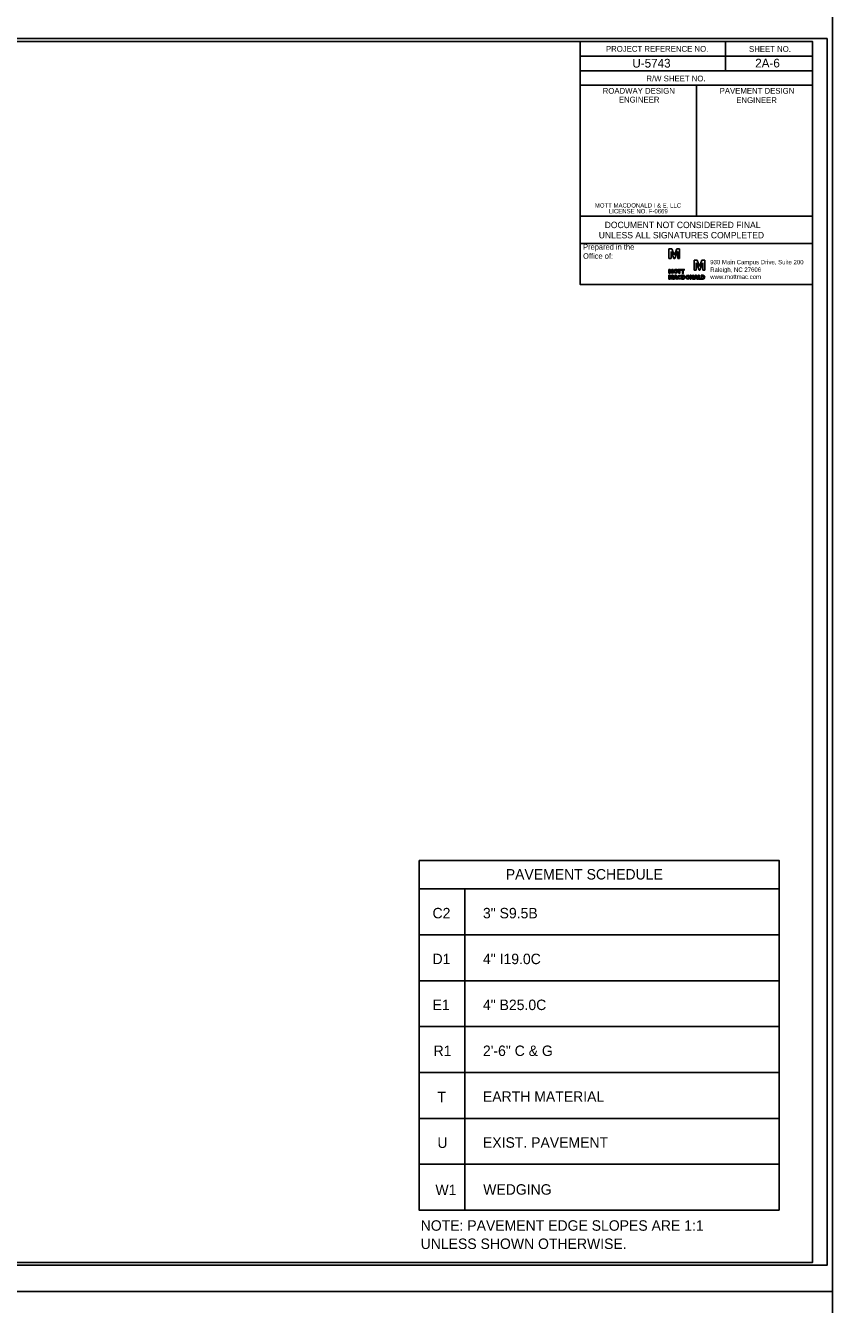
# Model space of a CAD drawing. Extents: x 1901670 to 1902225, y 193498 to 194278.
# Drawn here: x 1902064.8 to 1902134.2, y 193606.9 to 193716.9 of the extents above; entities that cross this region are included whole.
import ezdxf

# ---------------------------------------------------------------- set-up
doc = ezdxf.new("R2010")
doc.units = 0
for name, color, linetype in [('Old_Level_2', 7, 'Continuous'), ('Old_Level_42', 7, 'Continuous'), ('Old_Level_45', 7, 'Continuous'), ('Prop Dimension Text', 7, 'Continuous'), ('Prop Pavement Schedule Description CELL', 7, 'Continuous'), ('Sheet Border Standard 30in CELL', 7, 'Continuous'), ('Sheet Cutting Line CELL', 7, 'Continuous'), ('Sheet Data Field CELL', 7, 'Continuous'), ('Sheet Plot Border Inside CELL', 7, 'Continuous'), ('Sheet Plot Border Outside CELL', 7, 'Continuous'), ('Sheet Sticker Exception Certification CELL', 7, 'Continuous')]:
    doc.layers.add(name, color=color, linetype=linetype)

msp = doc.modelspace()

# ---------------------------------------------------------------- linework, layer by layer
at = {"layer": 'Old_Level_2'}
for p, q in [((1902120.44, 193697.7), (1902120.18, 193697.7)), ((1902120.18, 193697.7), (1902120.18, 193696.85)), ((1902120.18, 193696.85), (1902120.36, 193696.85)), ((1902120.36, 193696.85), (1902120.36, 193697.46)), ((1902120.36, 193697.46), (1902120.37, 193697.46)), ((1902120.37, 193697.46), (1902120.61, 193696.85)), ((1902120.64, 193697.17), (1902120.44, 193697.7)), ((1902120.61, 193696.85), (1902120.68, 193696.85)), ((1902120.65, 193697.17), (1902120.64, 193697.17)), ((1902120.64, 193697.17), (1902120.64, 193697.17)), ((1902120.85, 193697.7), (1902120.65, 193697.17)), ((1902120.65, 193697.17), (1902120.65, 193697.17)), ((1902120.68, 193696.85), (1902120.92, 193697.46)), ((1902121.1, 193697.7), (1902120.85, 193697.7)), ((1902120.92, 193697.46), (1902120.93, 193697.46)), ((1902120.93, 193697.46), (1902120.93, 193696.85)), ((1902120.93, 193696.85), (1902121.1, 193696.85)), ((1902121.1, 193696.85), (1902121.1, 193697.7)), ((1902120.28, 193695.92), (1902120.18, 193695.92)), ((1902120.18, 193695.92), (1902120.18, 193695.59)), ((1902120.25, 193695.59), (1902120.25, 193695.83)), ((1902120.25, 193695.83), (1902120.25, 193695.83)), ((1902120.25, 193695.83), (1902120.35, 193695.59)), ((1902120.25, 193695.83), (1902120.25, 193695.83)), ((1902120.36, 193695.72), (1902120.28, 193695.92)), ((1902120.44, 193695.92), (1902120.36, 193695.72)), ((1902120.38, 193695.59), (1902120.47, 193695.83)), ((1902120.54, 193695.92), (1902120.44, 193695.92)), ((1902120.47, 193695.83), (1902120.47, 193695.83)), ((1902120.47, 193695.83), (1902120.47, 193695.59)), ((1902120.47, 193695.83), (1902120.47, 193695.83)), ((1902120.47, 193695.83), (1902120.47, 193695.83)), ((1902120.54, 193695.59), (1902120.54, 193695.92)), ((1902120.54, 193695.59), (1902120.54, 193695.92)), ((1902122.6, 193696.71), (1902122.35, 193696.71)), ((1902122.35, 193696.71), (1902122.35, 193695.86)), ((1902122.35, 193695.86), (1902122.53, 193695.86)), ((1902122.53, 193695.86), (1902122.53, 193696.47)), ((1902122.53, 193696.47), (1902122.53, 193696.47)), ((1902122.53, 193696.47), (1902122.77, 193695.86)), ((1902122.8, 193696.18), (1902122.6, 193696.71)), ((1902122.77, 193695.86), (1902122.85, 193695.86)), ((1902122.81, 193696.18), (1902122.8, 193696.18)), ((1902122.8, 193696.18), (1902122.8, 193696.18)), ((1902123.01, 193696.71), (1902122.81, 193696.18)), ((1902122.81, 193696.18), (1902122.81, 193696.18)), ((1902122.85, 193695.86), (1902123.08, 193696.47)), ((1902123.27, 193696.71), (1902123.01, 193696.71)), ((1902123.08, 193696.47), (1902123.09, 193696.47)), ((1902123.09, 193696.47), (1902123.09, 193695.86)), ((1902123.09, 193695.86), (1902123.27, 193695.86)), ((1902123.27, 193695.86), (1902123.27, 193696.71)), ((1902120.18, 193695.59), (1902120.25, 193695.59)), ((1902120.28, 193695.41), (1902120.18, 193695.41)), ((1902120.18, 193695.41), (1902120.18, 193695.09)), ((1902120.18, 193695.09), (1902120.25, 193695.09)), ((1902120.25, 193695.09), (1902120.25, 193695.32)), ((1902120.25, 193695.32), (1902120.25, 193695.32)), ((1902120.25, 193695.32), (1902120.35, 193695.09)), ((1902120.36, 193695.21), (1902120.28, 193695.41)), ((1902120.35, 193695.59), (1902120.38, 193695.59)), ((1902120.35, 193695.09), (1902120.38, 193695.09)), ((1902120.44, 193695.41), (1902120.36, 193695.21)), ((1902120.38, 193695.09), (1902120.47, 193695.32)), ((1902120.54, 193695.41), (1902120.44, 193695.41)), ((1902120.47, 193695.59), (1902120.54, 193695.59)), ((1902120.47, 193695.32), (1902120.47, 193695.32)), ((1902120.47, 193695.32), (1902120.47, 193695.09)), ((1902120.47, 193695.09), (1902120.54, 193695.09)), ((1902120.54, 193695.09), (1902120.54, 193695.41)), ((1902121.22, 193695.16), (1902121.16, 193695.18)), ((1902121.22, 193695.16), (1902121.16, 193695.18)), ((1902121.17, 193695.31), (1902121.23, 193695.33)), ((1902121.17, 193695.31), (1902121.23, 193695.33)), ((1902121.42, 193695.41), (1902121.27, 193695.41)), ((1902121.27, 193695.41), (1902121.27, 193695.25)), ((1902121.27, 193695.25), (1902121.27, 193695.09)), ((1902121.27, 193695.09), (1902121.42, 193695.09)), ((1902121.34, 193695.15), (1902121.34, 193695.35)), ((1902121.34, 193695.35), (1902121.42, 193695.35)), ((1902121.42, 193695.15), (1902121.34, 193695.15)), ((1902122.96, 193695.41), (1902122.96, 193695.41)), ((1902123.1, 193695.41), (1902122.96, 193695.41)), ((1902122.96, 193695.41), (1902122.96, 193695.25)), ((1902122.96, 193695.25), (1902122.96, 193695.09)), ((1902122.96, 193695.09), (1902123.1, 193695.09)), ((1902123.02, 193695.15), (1902123.02, 193695.35)), ((1902123.02, 193695.35), (1902123.1, 193695.35)), ((1902123.1, 193695.15), (1902123.02, 193695.15)), ((1902123.1, 193695.35), (1902123.1, 193695.35))]:
    msp.add_line(p, q, dxfattribs=at)
for points in [[(1902120.95, 193695.86), (1902121.04, 193695.86), (1902121.04, 193695.59), (1902121.11, 193695.59), (1902121.11, 193695.86), (1902121.2, 193695.86), (1902121.2, 193695.92), (1902120.95, 193695.92), (1902120.95, 193695.86)], [(1902121.24, 193695.86), (1902121.34, 193695.86), (1902121.34, 193695.59), (1902121.41, 193695.59), (1902121.41, 193695.86), (1902121.5, 193695.86), (1902121.5, 193695.92), (1902121.24, 193695.92), (1902121.24, 193695.86)], [(1902120.58, 193695.09), (1902120.65, 193695.09), (1902120.68, 193695.14), (1902120.82, 193695.14), (1902120.84, 193695.09), (1902120.91, 193695.09), (1902120.79, 193695.41), (1902120.7, 193695.41), (1902120.58, 193695.09)], [(1902120.69, 193695.2), (1902120.75, 193695.34), (1902120.8, 193695.2), (1902120.69, 193695.2)], [(1902122.07, 193695.3), (1902122.07, 193695.3), (1902122.23, 193695.09), (1902122.29, 193695.09), (1902122.29, 193695.41), (1902122.23, 193695.41), (1902122.23, 193695.21), (1902122.07, 193695.41), (1902122, 193695.41), (1902122, 193695.09), (1902122.07, 193695.09), (1902122.07, 193695.3)], [(1902122.33, 193695.09), (1902122.41, 193695.09), (1902122.43, 193695.14), (1902122.57, 193695.14), (1902122.59, 193695.09), (1902122.67, 193695.09), (1902122.54, 193695.41), (1902122.46, 193695.41), (1902122.33, 193695.09)], [(1902122.45, 193695.2), (1902122.5, 193695.34), (1902122.56, 193695.2), (1902122.45, 193695.2)], [(1902122.92, 193695.09), (1902122.92, 193695.15), (1902122.78, 193695.15), (1902122.78, 193695.41), (1902122.71, 193695.41), (1902122.71, 193695.09), (1902122.92, 193695.09)], [(1902122.92, 193695.09), (1902122.92, 193695.15), (1902122.78, 193695.15), (1902122.78, 193695.41), (1902122.71, 193695.41), (1902122.71, 193695.09), (1902122.92, 193695.09), (1902122.92, 193695.15)]]:
    msp.add_lwpolyline(points, dxfattribs=at)
msp.add_arc((1902123.1, 193695.25), 0.162, 270, 90, dxfattribs=at)
for centre, major_axis, ratio in [((1902120.76, 193695.76), (0, 0.162), 0.993118), ((1902120.76, 193695.76), (0, 0.106), 0.916103), ((1902121.79, 193695.25), (0, 0.162), 0.993118), ((1902121.79, 193695.25), (0, 0.106), 0.916103)]:
    msp.add_ellipse(centre, major_axis=major_axis, ratio=ratio, dxfattribs=at)
for centre, major_axis, ratio, start_param, end_param in [((1902121.09, 193695.25), (0, 0.162), 0.993118, 5.246647, 10.366427), ((1902121.09, 193695.25), (0, 0.162), 0.993118, 5.246647, 10.366427), ((1902121.09, 193695.25), (0, 0.106), 0.916103, 5.276876, 9.424778), ((1902121.09, 193695.25), (0, 0.106), 0.916103, 5.276876, 10.296021), ((1902121.09, 193695.25), (0, 0.106), 0.916103, 3.141593, 4.012835), ((1902121.42, 193695.25), (0, -0.162), 0.930276, 0, 3.141593), ((1902121.42, 193695.25), (0, -0.101), 0.900832, 0, 3.141593), ((1902123.1, 193695.25), (0, -0.101), 0.900832, 0, 3.141593)]:
    msp.add_ellipse(centre, major_axis=major_axis, ratio=ratio, start_param=start_param, end_param=end_param, dxfattribs=at)
at = {"layer": 'Old_Level_42'}
msp.add_lwpolyline([(1902132.54, 193694.63), (1902112.54, 193694.63), (1902112.54, 193698.16)], dxfattribs=at)
at = {"layer": 'Prop Pavement Schedule Description CELL'}
msp.add_lwpolyline([(1902098.68, 193645.08), (1902129.65, 193645.08), (1902129.65, 193642.63), (1902098.68, 193642.63)], close=True, dxfattribs=at)
for points in [[(1902102.63, 193638.68), (1902098.68, 193638.68), (1902098.68, 193642.63), (1902129.65, 193642.63), (1902129.65, 193638.68), (1902102.63, 193638.68), (1902102.63, 193642.63)], [(1902102.63, 193634.73), (1902098.68, 193634.73), (1902098.68, 193638.68), (1902129.65, 193638.68), (1902129.65, 193634.73), (1902102.63, 193634.73), (1902102.63, 193638.68)], [(1902102.63, 193630.79), (1902098.68, 193630.79), (1902098.68, 193634.73), (1902129.65, 193634.73), (1902129.65, 193630.79), (1902102.63, 193630.79), (1902102.63, 193634.73)], [(1902102.63, 193626.84), (1902098.68, 193626.84), (1902098.68, 193630.79), (1902129.65, 193630.79), (1902129.65, 193626.84), (1902102.63, 193626.84), (1902102.63, 193630.79)], [(1902102.63, 193622.89), (1902098.68, 193622.89), (1902098.68, 193626.84), (1902129.65, 193626.84), (1902129.65, 193622.89), (1902102.63, 193622.89), (1902102.63, 193626.84)], [(1902102.63, 193618.95), (1902098.68, 193618.95), (1902098.68, 193622.89), (1902129.65, 193622.89), (1902129.65, 193618.95), (1902102.63, 193618.95), (1902102.63, 193622.89)], [(1902102.63, 193615), (1902098.68, 193615), (1902098.68, 193618.95), (1902129.65, 193618.95), (1902129.65, 193615), (1902102.63, 193615), (1902102.63, 193618.95)]]:
    msp.add_lwpolyline(points, dxfattribs=at)
at = {"layer": 'Sheet Border Standard 30in CELL'}
for p, q in [((1902125.04, 193715.51), (1902125.04, 193713.01)), ((1902112.54, 193714.26), (1902132.54, 193714.26)), ((1902112.54, 193713.01), (1902132.54, 193713.01)), ((1902112.54, 193713.01), (1902112.54, 193711.76)), ((1902112.54, 193713.01), (1902132.54, 193713.01)), ((1902122.54, 193711.76), (1902122.54, 193700.51))]:
    msp.add_line(p, q, dxfattribs=at)
for points in [[(1902132.54, 193715.51), (1901982.54, 193715.51), (1901982.54, 193610.51), (1902132.54, 193610.51)], [(1902112.54, 193715.51), (1902132.54, 193715.51), (1902132.54, 193713.01), (1902112.54, 193713.01)], [(1902112.54, 193711.76), (1902122.54, 193711.76), (1902122.54, 193700.51), (1902112.54, 193700.51)], [(1902122.54, 193711.76), (1902132.54, 193711.76), (1902132.54, 193700.51), (1902122.54, 193700.51)]]:
    msp.add_lwpolyline(points, close=True, dxfattribs=at)
at = {"layer": 'Sheet Cutting Line CELL'}
for p, q in [((1901965.84, 193608.01), (1902134.24, 193608.01)), ((1902134.24, 193608.01), (1901965.84, 193608.01))]:
    msp.add_line(p, q, dxfattribs=at)
at = {"layer": 'Sheet Plot Border Inside CELL'}
msp.add_lwpolyline([(1902133.79, 193715.77), (1901967.14, 193715.77), (1901967.14, 193610.26), (1902133.79, 193610.26)], close=True, dxfattribs=at)
at = {"layer": 'Sheet Plot Border Outside CELL'}
for points in [[(1902134.24, 193718.01), (1901965.84, 193718.01), (1901965.84, 193608.01), (1902134.24, 193608.01)], [(1902134.24, 193608.01), (1901965.84, 193608.01), (1901965.84, 193498.01), (1902134.24, 193498.01)]]:
    msp.add_lwpolyline(points, close=True, dxfattribs=at)
at = {"layer": 'Sheet Sticker Exception Certification CELL'}
for p, q in [((1902112.54, 193698.16), (1902112.54, 193700.51)), ((1902112.54, 193700.51), (1902132.54, 193700.51)), ((1902132.54, 193700.51), (1902132.54, 193698.16)), ((1902132.54, 193698.16), (1902112.54, 193698.16))]:
    msp.add_line(p, q, dxfattribs=at)

# ---------------------------------------------------------------- texts
at = {"layer": 'Old_Level_2'}
for s, height, p in [('Prepared in the ', 0.4819, (1902112.79, 193697.61)), ('Office of:', 0.482, (1902112.79, 193696.83))]:
    msp.add_text(s, height=height, dxfattribs=at).set_placement(p)
for s, p in [('930 Main Campus Drive, Suite 200', (1902123.73, 193696.36)), ('Raleigh, NC 27606', (1902123.73, 193695.71)), ('www.mottmac.com ', (1902123.73, 193695.1))]:
    msp.add_text(s, height=0.375, rotation=360, dxfattribs=at).set_placement(p)
at = {"layer": 'Old_Level_45'}
for s, p in [('MOTT MACDONALD I & E, LLC', (1902113.8, 193701.24)), (' LICENSE NO. F-0669', (1902114.87, 193700.74))]:
    msp.add_text(s, height=0.375, rotation=360, dxfattribs=at).set_placement(p)
at = {"layer": 'Prop Dimension Text'}
msp.add_text('PAVEMENT SCHEDULE', height=0.9, dxfattribs=at).set_placement((1902106.14, 193643.44))
at = {"layer": 'Prop Pavement Schedule Description CELL'}
for s, p in [('C2', (1902099.84, 193640.1)), ('    3" S9.5B', (1902102.84, 193640.1)), ('D1', (1902099.84, 193636.16)), ('    4" I19.0C', (1902102.84, 193636.16)), ('E1', (1902099.84, 193632.21)), ('    4" B25.0C', (1902102.84, 193632.21)), ('R1', (1902099.93, 193628.26)), ('    2\'-6" C & G', (1902102.84, 193628.26)), ('T', (1902100.25, 193624.28)), ('    EARTH MATERIAL', (1902102.84, 193624.32)), ('U', (1902100.26, 193620.35)), ('    EXIST. PAVEMENT', (1902102.84, 193620.37)), ('W1', (1902100.09, 193616.29)), ('    WEDGING', (1902102.86, 193616.33)), ('NOTE: PAVEMENT EDGE SLOPES ARE 1:1', (1902098.82, 193613.23)), ('UNLESS SHOWN OTHERWISE.', (1902098.82, 193611.66))]:
    msp.add_text(s, height=0.9, dxfattribs=at).set_placement(p)
at = {"layer": 'Sheet Border Standard 30in CELL'}
for s, p in [('PROJECT REFERENCE NO.', (1902114.76, 193714.64)), ('SHEET NO.', (1902127.07, 193714.63)), ('R/W SHEET NO.', (1902118.24, 193712.09)), ('ROADWAY DESIGN', (1902114.48, 193711.03)), ('PAVEMENT DESIGN', (1902124.54, 193711.03)), ('ENGINEER', (1902115.87, 193710.27)), ('ENGINEER', (1902125.97, 193710.23))]:
    msp.add_text(s, height=0.5, dxfattribs=at).set_placement(p)
at = {"layer": 'Sheet Data Field CELL'}
for s, p in [('U-5743', (1902117.03, 193713.28)), ('2A-6', (1902127.6, 193713.29))]:
    msp.add_text(s, height=0.75, dxfattribs=at).set_placement(p)
at = {"layer": 'Sheet Sticker Exception Certification CELL'}
for s, p in [('UNLESS ALL SIGNATURES COMPLETED', (1902114.14, 193698.59)), ('DOCUMENT NOT CONSIDERED FINAL', (1902114.65, 193699.47))]:
    msp.add_text(s, height=0.55, dxfattribs=at).set_placement(p)

doc.saveas('drawing.dxf')
